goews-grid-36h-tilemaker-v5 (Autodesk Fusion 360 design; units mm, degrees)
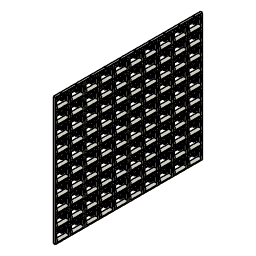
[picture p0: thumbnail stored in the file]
parameter "Spacing" = 42
parameter "HorizontalSize" = 420 (= "( HorizontalQTY * 42 ) * 1 mm")
parameter "VerticalSize" = 363.73 (= "( VerticalQTY * 36.373 ) * 1 mm")
parameter "VSpacing" = 36.373
base_feature "Base Feature" bodies "GOEWS Square"
delete_face "DeleteFace2"
move_face "MoveFace2"
move_face "MoveFace3"
sketch "Sketch3" plane through (0, 0, 0) normal (1, 0, 0) x axis (0, 1, 0)
  line L1 (20.5, -14.624) -> (-20.5, -14.624)
  line L2 (20.5, 20.749) -> (20.5, -14.624)
  line L3 (-20.5, 20.749) -> (20.5, 20.749)
  line L4 (-20.5, -14.624) -> (-20.5, 20.749)
  line L5 (-15.5, -12.1244) -> (15.5, -12.1244)
  line L6 (-15.5, -4.1244) -> (-15.5, -12.1244)
  line L7 (-18, -1.6244) -> (-15.5, -4.1244)
  line L8 (-18, 9.8756) -> (-18, -1.6244)
  line L9 (-8.5448, 9.8756) -> (-18, 9.8756)
  line L10 (18, 9.8756) -> (8.5448, 9.8756)
  line L11 (18, -1.6244) -> (18, 9.8756)
  line L12 (15.5, -4.1244) -> (18, -1.6244)
  line L13 (15.5, -12.1244) -> (15.5, -4.1244)
  line L14 (-18, 20.749) -> (-18, 9.8756)
  line L15 (20.5, 15.3123) -> (-18, 15.3123)
  line L16 (18, 20.749) -> (18, 9.8756)
  line L17 (0, 15.3123) -> (0, 3.7017)
  line L18 (-12.7, 15.3123) -> (0, 15.3123)
  line L19 (12.7, 15.3123) -> (0, 15.3123)
  line L20 (-12.7, 17.3123) -> (-12.7, 15.3123)
  line L21 (12.7, 17.3123) -> (12.7, 15.3123)
  circle C1 centre (0, 12.7017) radius 7.1612
  arc A1 centre (0, 12.7017) radius 9 clockwise from (8.5448, 9.8756) to (-8.5448, 9.8756)
  circle C2 centre (-12.7, 15.3123) radius 2
  circle C3 centre (12.7, 15.3123) radius 2
  circle C4 centre (-12.7, 15.3123) radius 4
  circle C5 centre (12.7, 15.3123) radius 4
  point P11 (-18, 9.8756)
  point P17 (-18, 9.8756)
  point P18 (-18, 20.749)
  point P19 (-18, 15.3123)
  point P20 (20.5, 15.3123)
  point P14 (18, 9.8756)
  point P21 (18, 9.8756)
  point P22 (18, 20.749)
  point P23 (0, 3.7017)
  point P24 (0, 15.3123)
  point P25 (-12.7, 15.3123)
  point P27 (-12.7, 15.3123)
  point P26 (12.7, 15.3123)
  point P28 (12.7, 15.3123)
  point P29 (-12.7, 15.3123)
  point P32 (-12.7, 17.3123)
  point P31 (-12.7, 15.3123)
  point P34 (12.7, 17.3123)
  point P33 (12.7, 15.3123)
  coincident P11 P17
  coincident L3 P18
  perpendicular L3 L14
  midpoint L14 P19
  coincident L2 P20
  perpendicular L2 L15
  coincident P14 P21
  coincident L3 P22
  perpendicular L3 L16
  midpoint A1 P23
  coincident L15 P24
  perpendicular L15 L17
  perpendicular L17 L18
  perpendicular L17 L19
  coincident P25 P27
  coincident P26 P28
  coincident P25 P29
  concentric C3 C5
  coincident C2 P32
  perpendicular L18 L20
  coincident P29 P31
  coincident C3 P34
  perpendicular L15 L21
  coincident P28 P33
  dimension "d18" distance P24 P25 = 12.7 (= "0.5")
  dimension "d19" distance P24 P26 = 12.7 (= "0.5")
  dimension "d20" diameter C2 = 4
  dimension "d21" diameter C3 = 4
  dimension "d22" diameter C4 = 8
  dimension "d23" diameter C5 = 8
extrude "Extrude7" cut sketch "Sketch3" profile of C2 C3 against normal blind 6
extrude "Extrude5" cut sketch "Sketch3" profile of C2 C3 C4 C5 against normal blind 1
sketch "Sketch1" plane through (0, 0, 0) normal (1, 0, 0) x axis (0, 1, 0)
  line L1 (20.5, -14.624) -> (-20.5, -14.624)
  line L2 (20.5, 20.749) -> (20.5, -14.624)
  line L3 (-20.5, 20.749) -> (20.5, 20.749)
  line L4 (-20.5, -14.624) -> (-20.5, 20.749)
  line L5 (-15.5, -12.1244) -> (15.5, -12.1244)
  line L6 (-15.5, -4.1244) -> (-15.5, -12.1244)
  line L7 (-18, -1.6244) -> (-15.5, -4.1244)
  line L8 (-18, 9.8756) -> (-18, -1.6244)
  line L9 (-8.5448, 9.8756) -> (-18, 9.8756)
  line L10 (18, 9.8756) -> (8.5448, 9.8756)
  line L11 (18, -1.6244) -> (18, 9.8756)
  line L12 (15.5, -4.1244) -> (18, -1.6244)
  line L13 (15.5, -12.1244) -> (15.5, -4.1244)
  circle C1 centre (0, 12.7017) radius 7.1612
  arc A1 centre (0, 12.7017) radius 9 clockwise from (8.5448, 9.8756) to (-8.5448, 9.8756)
  circle C2 centre (0, -16.3122) radius 4.6
  circle C3 centre (0, -16.3122) radius 2.3
  circle C4 centre (-12.7, 15.3123) radius 4
  circle C5 centre (12.7, 15.3123) radius 4
  concentric C2 C3
  dimension "d10" diameter C2 = 9.2
  dimension "d14" diameter C3 = 4.6
chamfer "Chamfer4" distance 2
rectangular_pattern "R-Pattern1" uSpaceDistance 42 (= "Spacing") vSpaceDistance 36.373 (= "VSpacing") bodies "GOEWS Square (1)", "GOEWS Square (3)", "GOEWS Square (5)", "GOEWS Square (4)", "GOEWS Square (6)", "GOEWS Square (36)", "GOEWS Square (37)", "GOEWS Square (38)"
combine "Combine1" bodies "GOEWS Square (36)", "GOEWS Square (37)", "GOEWS Square (40)", "GOEWS Square (17)", "GOEWS Square (13)", "GOEWS Square (21)", "GOEWS Square (8)", "GOEWS Square (1)"
named bodies: "GOEWS Square", "GOEWS Square (10)", "GOEWS Square (20)", "GOEWS Square (2)", "GOEWS Square (1)", "GOEWS Square (3)", "GOEWS Square (5)", "GOEWS Square (7)", "GOEWS Square (8)", "GOEWS Square (9)", "GOEWS Square (12)", "GOEWS Square (13)", "GOEWS Square (14)", "GOEWS Square (16)", "GOEWS Square (17)", "GOEWS Square (18)", "GOEWS Square (4)", "GOEWS Square (6)", "GOEWS Square (11)", "GOEWS Square (15)", "GOEWS Square (19)", "GOEWS Square (21)", "GOEWS Square (22)", "GOEWS Square (23)", "GOEWS Square (24)", "GOEWS Square (25)", "GOEWS Square (26)", "GOEWS Square (27)", "GOEWS Square (28)", "GOEWS Square (29)", "GOEWS Square (30)", "GOEWS Square (31)", "GOEWS Square (32)", "GOEWS Square (33)", "GOEWS Square (34)", "GOEWS Square (35)", "GOEWS Square (36)", "GOEWS Square (37)", "GOEWS Square (38)", "GOEWS Square (39)", "GOEWS Square (40)", "GOEWS Square (41)", "GOEWS Square (42)", "GOEWS Square (43)", "GOEWS Square (44)", "GOEWS Square (45)", "GOEWS Square (46)", "GOEWS Square (47)", "GOEWS Square (48)", "GOEWS Square (49)", "GOEWS Square (50)", "GOEWS Square (51)", "GOEWS Square (52)", "GOEWS Square (53)", "GOEWS Square (54)", "GOEWS Square (55)", "GOEWS Square (56)", "GOEWS Square (57)", "GOEWS Square (58)", "GOEWS Square (59)"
